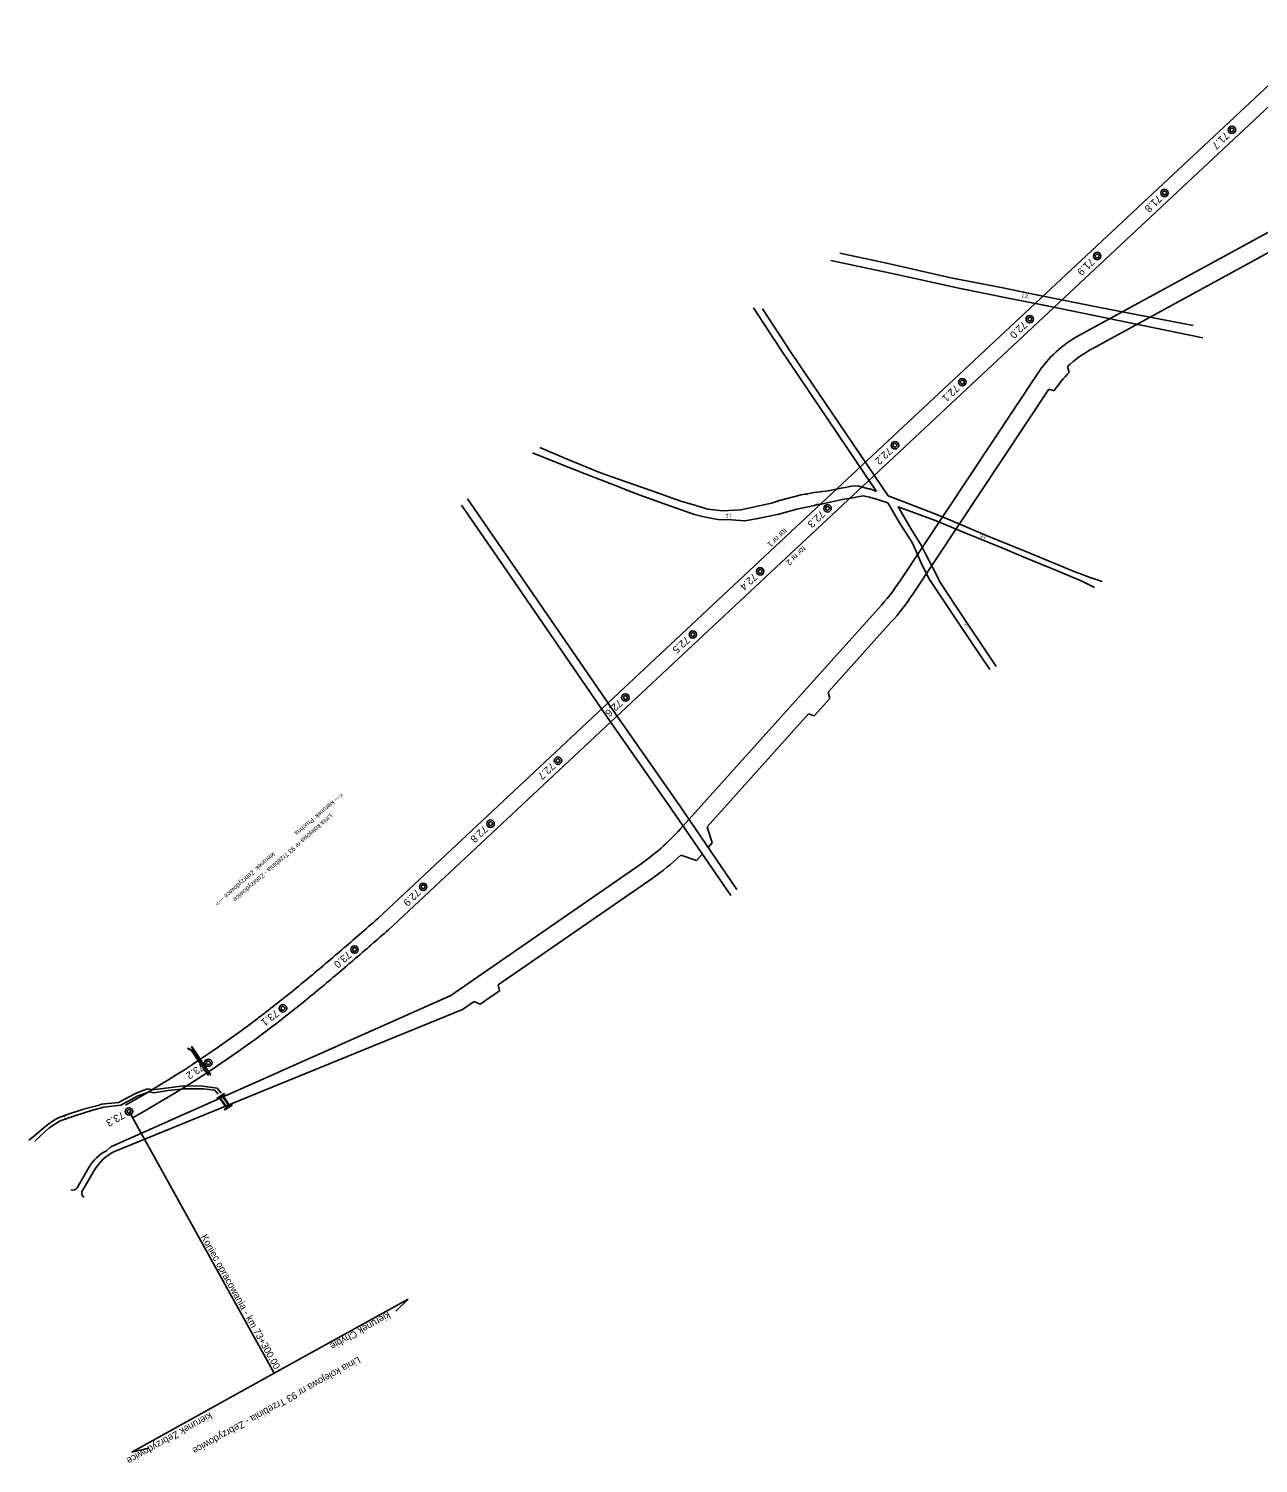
# Model space of a CAD drawing. Extents: x 6541740 to 6556805, y 5525233 to 5530361.
# Drawn here: x 6554409 to 6554742, y 5525232.8 to 5525621.4 of the extents above; entities that cross this region are included whole.
import ezdxf

# ---------------------------------------------------------------- set-up
doc = ezdxf.new("R2010")
doc.units = 0
for name, color, linetype in [('Default', 7, 'Continuous'), ('TOR_PS_OPIS_T-numeracja torow i rozjazdow', 7, 'Continuous'), ('TOR_SCH-hektometry', 7, 'Continuous'), ('TOR_SCH-obiekty projektowane', 7, 'Continuous'), ('TOR_SCH-opisy glowne', 7, 'Continuous'), ('TOR_SCH-przejazdy+drogi istniejace', 7, 'Continuous'), ('TOR_SCH-przejazdy+drogi projektowane', 7, 'Continuous'), ('TOR_SCH-tory projektowane', 7, 'Continuous')]:
    doc.layers.add(name, color=color, linetype=linetype)

# ---------------------------------------------------------------- blocks, each defined once
blk = doc.blocks.new('4010_1')
at = {"layer": 'Default'}
for radius in [0.75, 0.375]:
    blk.add_circle((0, 0), radius, dxfattribs=at)

msp = doc.modelspace()

# ---------------------------------------------------------------- linework, layer by layer
at = {"layer": 'TOR_SCH-obiekty projektowane'}
for p, q in [((6554453.97, 5525344.45), (6554453.14, 5525345.69)), ((6554454.09, 5525344.41), (6554453.2, 5525345.73)), ((6554453.15, 5525344.65), (6554456.99, 5525338.9)), ((6554453.55, 5525344.17), (6554457.11, 5525338.86)), ((6554453.97, 5525344.45), (6554457.52, 5525339.14)), ((6554454.96, 5525342.96), (6554454.02, 5525344.37)), ((6554454.09, 5525344.41), (6554457.53, 5525339.26)), ((6554456.99, 5525338.9), (6554457.68, 5525337.87)), ((6554457.11, 5525338.86), (6554457.75, 5525337.9)), ((6554457.35, 5525338.36), (6554457.89, 5525338.72)), ((6554457.39, 5525338.3), (6554457.93, 5525338.66)), ((6554457.52, 5525339.14), (6554458.27, 5525338.02)), ((6554457.53, 5525339.26), (6554458.33, 5525338.06)), ((6554460.65, 5525331.93), (6554462.55, 5525329.1)), ((6554460.8, 5525332.02), (6554462.69, 5525329.19)), ((6554461.41, 5525332.41), (6554463.31, 5525329.58)), ((6554461.56, 5525332.5), (6554463.45, 5525329.67))]:
    msp.add_line(p, q, dxfattribs=at)
for points in [[(6554453.14, 5525345.69), (6554453.2, 5525345.73)], [(6554453.55, 5525344.17), (6554453.2, 5525344.7), (6554452.14, 5525345.26), (6554452.06, 5525345.21)], [(6554452.06, 5525345.21), (6554453.15, 5525344.65)], [(6554453.15, 5525344.64), (6554453.69, 5525345)], [(6554453.19, 5525344.58), (6554453.73, 5525344.94)], [(6554457.68, 5525337.87), (6554457.75, 5525337.9)], [(6554458.33, 5525338.06), (6554458.27, 5525338.02)]]:
    msp.add_lwpolyline(points, dxfattribs=at)
for points in [[(6554461.99, 5525333.01), (6554462.1, 5525332.84), (6554460.13, 5525331.6), (6554460.02, 5525331.76)], [(6554463.99, 5525330.01), (6554464.1, 5525329.84), (6554462.12, 5525328.6), (6554462.02, 5525328.76)]]:
    msp.add_lwpolyline(points, close=True, dxfattribs=at)
at = {"layer": 'TOR_SCH-opisy glowne'}
for p, q in [((6554436.19, 5525328.13), (6554475.54, 5525257.21)), ((6554476.34, 5525257.66), (6554511.76, 5525277.31)), ((6554511.76, 5525277.31), (6554508.41, 5525274.02)), ((6554476.34, 5525257.66), (6554437, 5525235.83)), ((6554437, 5525235.81), (6554441.57, 5525236.92))]:
    msp.add_line(p, q, dxfattribs=at)
at = {"layer": 'TOR_SCH-przejazdy+drogi istniejace'}
for points in [[(6554724.4, 5525541.04), (6554699.11, 5525545.93), (6554682.35, 5525549.25), (6554672.35, 5525551.33), (6554658.77, 5525553.93), (6554641.79, 5525557.81), (6554628.67, 5525560.6)], [(6554727.02, 5525537.73), (6554684.42, 5525546.42), (6554674.7, 5525548.35), (6554660.94, 5525551.16), (6554644.1, 5525554.84), (6554626.22, 5525558.63)], [(6554638.63, 5525496.09), (6554612.47, 5525534.9), (6554605.27, 5525545.87)], [(6554607.75, 5525545.53), (6554615.61, 5525533.57), (6554641.73, 5525494.9)], [(6554545.42, 5525506.55), (6554553.79, 5525503.19), (6554559.75, 5525500.87), (6554567.67, 5525497.76), (6554573.38, 5525495.55), (6554579.87, 5525493.22), (6554585.68, 5525491.13), (6554589.37, 5525489.82), (6554591.85, 5525489.25), (6554595.66, 5525488.5), (6554599.38, 5525488.39), (6554602.99, 5525488.11), (6554606.5, 5525488.73), (6554612.19, 5525489.92), (6554617.07, 5525491.28), (6554621.85, 5525492.29)], [(6554619.19, 5525495.33), (6554618.24, 5525495.15), (6554612.3, 5525493.6), (6554610.19, 5525492.94), (6554601.87, 5525491.08), (6554596.87, 5525490.88), (6554592.94, 5525491.33), (6554588.76, 5525492.52), (6554585.93, 5525493.41), (6554577.01, 5525496.49), (6554568.48, 5525499.5), (6554563.89, 5525501.11), (6554559.93, 5525502.78), (6554554.87, 5525504.8), (6554547.4, 5525507.95)], [(6554633.61, 5525497.56), (6554632.81, 5525497.64), (6554631.84, 5525497.54), (6554630.94, 5525497.36), (6554630.22, 5525497.16), (6554629.52, 5525497.06), (6554625.51, 5525496.3), (6554621.76, 5525495.78), (6554619.93, 5525495.44), (6554619.65, 5525495.33), (6554619.19, 5525495.33)], [(6554638.63, 5525496.09), (6554636.62, 5525496.88), (6554636.73, 5525496.74), (6554633.93, 5525497.51), (6554633.61, 5525497.56)], [(6554527.88, 5525494.07), (6554540.88, 5525475.2), (6554567.9, 5525435.86), (6554585.5, 5525410.63), (6554600.82, 5525388.31)], [(6554621.85, 5525492.29), (6554622.41, 5525492.58), (6554623.2, 5525492.57), (6554623.65, 5525492.66), (6554629.31, 5525493.88), (6554632.26, 5525494.32)], [(6554632.26, 5525494.32), (6554632.99, 5525494.5), (6554633.58, 5525494.65), (6554634.97, 5525494.86), (6554636.75, 5525494.55), (6554638.89, 5525493.94), (6554641.66, 5525492.98), (6554641.66, 5525492.98)], [(6554699.68, 5525471.74), (6554696.21, 5525472.86), (6554692.18, 5525474.4), (6554679.02, 5525479.78), (6554668.55, 5525484.05), (6554658.86, 5525488.2), (6554654.43, 5525490.06), (6554647.22, 5525492.79), (6554641.73, 5525494.9)], [(6554526.2, 5525492.41), (6554538.49, 5525474.58), (6554562.95, 5525438.96), (6554565.52, 5525435.22), (6554583.11, 5525410), (6554599.17, 5525386.62)], [(6554641.66, 5525492.98), (6554645.03, 5525487.31), (6554648.28, 5525482.22), (6554649.14, 5525480.27), (6554650.56, 5525477.1), (6554652.76, 5525472.51), (6554661.3, 5525459.79), (6554669.3, 5525447.89)], [(6554697.68, 5525470.04), (6554693.99, 5525471.87), (6554687.82, 5525474.48), (6554678.3, 5525478.39), (6554672.34, 5525480.92), (6554662.36, 5525485.01), (6554655.02, 5525488.04), (6554644.45, 5525491.88), (6554647.87, 5525486.03), (6554650.68, 5525481.51), (6554652.1, 5525478.85), (6554653.89, 5525475.43), (6554655.94, 5525471.3), (6554659.93, 5525465.32), (6554671.03, 5525448.65)], [(6554428.76, 5525330.1), (6554433.36, 5525330.54), (6554437.99, 5525333.02), (6554440.9, 5525334.16), (6554441.35, 5525334.24), (6554442.63, 5525334.01), (6554446.77, 5525334.55), (6554451, 5525335.08), (6554456.2, 5525335.03), (6554460.05, 5525334.44), (6554461.11, 5525333.07)], [(6554460.29, 5525332.79), (6554459.4, 5525333.89), (6554456.33, 5525334.31), (6554451.33, 5525334.28), (6554446.79, 5525333.78), (6554442.94, 5525333.19), (6554441.71, 5525333.49), (6554438.58, 5525332.33)], [(6554409.03, 5525320.35), (6554410.24, 5525321.26), (6554412.56, 5525323.29), (6554413.73, 5525324.28), (6554415.48, 5525325.53), (6554416.84, 5525326.3), (6554419.2, 5525327.2), (6554423.9, 5525328.74), (6554428.13, 5525329.86), (6554428.76, 5525330.1)], [(6554429.38, 5525329.33), (6554433.97, 5525329.81), (6554438.58, 5525332.33)], [(6554429.38, 5525329.33), (6554425.99, 5525328.43), (6554421.76, 5525327.07), (6554417.52, 5525325.58), (6554414.57, 5525323.72), (6554412.22, 5525321.52), (6554410.77, 5525320.15), (6554410.77, 5525320.15)]]:
    msp.add_lwpolyline(points, dxfattribs=at)
at = {"layer": 'TOR_SCH-przejazdy+drogi projektowane'}
for p, q in [((6554764.56, 5525577.16), (6554693.62, 5525538.42)), ((6554764.57, 5525571.64), (6554696.97, 5525534.73)), ((6554690.81, 5525528.3), (6554690.31, 5525529.91)), ((6554682.18, 5525527.94), (6554644.98, 5525471.87)), ((6554685.29, 5525523.82), (6554648.44, 5525468.28)), ((6554686.75, 5525523.38), (6554685.29, 5525523.82)), ((6554639.18, 5525464.37), (6554585.45, 5525404.6)), ((6554642.61, 5525460.74), (6554625.48, 5525441.68)), ((6554621.76, 5525435.3), (6554626.01, 5525440.03)), ((6554625.48, 5525441.68), (6554626.01, 5525440.03)), ((6554620.22, 5525435.83), (6554592.72, 5525405.24)), ((6554620.22, 5525435.83), (6554621.76, 5525435.3)), ((6554592.72, 5525405.24), (6554594.12, 5525400.87)), ((6554593.03, 5525399.66), (6554594.12, 5525400.87)), ((6554585.59, 5525397.58), (6554589.84, 5525396.11)), ((6554589.84, 5525396.11), (6554591.43, 5525397.88)), ((6554574.48, 5525394.95), (6554523.3, 5525359.52)), ((6554577.86, 5525391.28), (6554536.15, 5525362.4)), ((6554536.15, 5525362.4), (6554536.54, 5525360.86)), ((6554523.3, 5525359.52), (6554431.28, 5525318.52)), ((6554523.3, 5525359.52), (6554523.09, 5525359.38)), ((6554529.64, 5525357.89), (6554526.51, 5525355.72)), ((6554529.64, 5525357.89), (6554531.27, 5525357.22)), ((6554531.27, 5525357.22), (6554536.54, 5525360.86)), ((6554526.51, 5525355.72), (6554432.22, 5525317.29)), ((6554430.11, 5525317.51), (6554431.28, 5525318.52)), ((6554425.32, 5525312.99), (6554422.14, 5525307.48)), ((6554426.78, 5525312.15), (6554423.56, 5525306.69))]:
    msp.add_line(p, q, dxfattribs=at)
for centre, radius, start, end in [((6554435.28, 5525307.24), 11.5, 116.6963, 149.9534), ((6554438.14, 5525305.58), 13.12, 116.8109, 149.9534), ((6554421, 5525308.14), 1.31, 246.6218, 329.9534), ((6554424.7, 5525306.04), 1.31, 149.9534, 240.4975)]:
    msp.add_arc(centre, radius, start, end, dxfattribs=at)
for centre, major_axis, start_param, end_param in [((6555030.42, 5525166.83), (-343.43, 366.83), 6.218732, 6.342331), ((6555030.42, 5525166.83), (-340.01, 363.18), 6.218732, 6.284285), ((6555030.42, 5525166.83), (-338.99, 362.08), 0.00704, 0.058091), ((6553953.68, 5526188.7), (-681.73, 728.18), 3.16316, 3.200739), ((6553953.68, 5526188.7), (-685.15, 731.83), 3.16316, 3.200739), ((6553899.95, 5526128.94), (-681.73, 728.18), 3.104606, 3.16316), ((6553899.95, 5526128.94), (-685.15, 731.83), 3.104606, 3.144299)]:
    msp.add_ellipse(centre, major_axis=major_axis, ratio=0.25, start_param=start_param, end_param=end_param, dxfattribs=at)
at = {"layer": 'TOR_SCH-tory projektowane'}
for p, q in [((6554761.12, 5525621.44), (6554611.29, 5525481.24)), ((6554764.11, 5525618.43), (6554614.16, 5525478.15)), ((6554611.29, 5525481.24), (6554503.49, 5525380.32)), ((6554614.16, 5525478.15), (6554506.36, 5525377.25))]:
    msp.add_line(p, q, dxfattribs=at)
for points in [[(6554503.49, 5525380.32), (6554502.88, 5525379.79), (6554502.28, 5525379.26), (6554501.67, 5525378.74), (6554501.07, 5525378.21), (6554500.46, 5525377.68), (6554499.86, 5525377.16), (6554499.25, 5525376.63), (6554498.65, 5525376.11), (6554498.04, 5525375.58), (6554497.44, 5525375.06), (6554496.83, 5525374.53), (6554496.22, 5525374.01), (6554495.62, 5525373.48), (6554495.01, 5525372.96), (6554494.4, 5525372.44), (6554493.79, 5525371.91), (6554493.18, 5525371.39), (6554492.58, 5525370.87), (6554491.97, 5525370.35), (6554491.36, 5525369.83), (6554490.75, 5525369.31), (6554490.14, 5525368.79), (6554489.52, 5525368.27), (6554488.91, 5525367.75), (6554488.3, 5525367.23), (6554487.69, 5525366.72), (6554487.07, 5525366.2), (6554486.46, 5525365.68), (6554485.84, 5525365.17), (6554485.23, 5525364.66), (6554484.61, 5525364.14), (6554483.99, 5525363.63), (6554483.38, 5525363.12), (6554482.76, 5525362.61), (6554482.14, 5525362.1), (6554481.52, 5525361.59), (6554480.89, 5525361.09), (6554480.27, 5525360.58), (6554479.65, 5525360.08), (6554479.02, 5525359.58), (6554478.4, 5525359.07), (6554477.77, 5525358.57), (6554477.14, 5525358.07), (6554476.52, 5525357.57), (6554475.89, 5525357.08), (6554475.26, 5525356.58), (6554474.62, 5525356.09), (6554473.99, 5525355.6), (6554473.36, 5525355.1), (6554472.72, 5525354.62), (6554472.09, 5525354.13), (6554471.45, 5525353.64), (6554470.81, 5525353.16)], [(6554506.55, 5525377.44), (6554505.95, 5525376.91), (6554505.35, 5525376.39), (6554504.75, 5525375.87), (6554504.15, 5525375.35), (6554503.55, 5525374.83), (6554502.95, 5525374.31), (6554502.35, 5525373.79), (6554501.76, 5525373.27), (6554501.16, 5525372.75), (6554500.56, 5525372.23), (6554499.96, 5525371.71), (6554499.36, 5525371.19), (6554498.76, 5525370.68), (6554498.16, 5525370.16), (6554497.55, 5525369.64), (6554496.95, 5525369.12), (6554496.35, 5525368.61), (6554495.75, 5525368.09), (6554495.15, 5525367.57), (6554494.54, 5525367.06), (6554493.94, 5525366.54), (6554493.34, 5525366.03), (6554492.73, 5525365.52), (6554492.13, 5525365), (6554491.52, 5525364.49), (6554490.91, 5525363.98), (6554490.31, 5525363.47), (6554489.7, 5525362.96), (6554489.09, 5525362.45), (6554488.48, 5525361.94), (6554487.87, 5525361.44), (6554487.26, 5525360.93), (6554486.65, 5525360.43), (6554486.03, 5525359.92), (6554485.42, 5525359.42), (6554484.81, 5525358.92), (6554484.19, 5525358.42), (6554483.58, 5525357.92), (6554482.96, 5525357.42), (6554482.34, 5525356.92), (6554481.72, 5525356.42), (6554481.1, 5525355.93), (6554480.48, 5525355.43), (6554479.86, 5525354.94), (6554479.24, 5525354.45), (6554478.61, 5525353.96), (6554477.99, 5525353.47), (6554477.36, 5525352.98), (6554476.74, 5525352.5), (6554476.11, 5525352.01), (6554475.48, 5525351.53), (6554474.85, 5525351.05)]]:
    msp.add_lwpolyline(points, dxfattribs=at)
for centre, radius, start, end in [((6554282.16, 5525602.29), 312.5, 299.3305, 307.1342), ((6554285.04, 5525600.56), 313.5, 299.0221, 307.2608)]:
    msp.add_arc(centre, radius, start, end, dxfattribs=at)

# ---------------------------------------------------------------- block references
at = {"layer": 'TOR_SCH-hektometry'}
for p, xscale, yscale, rotation in [((6554734.86, 5525594.03), 1.3459632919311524, 1.345963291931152, 18.110655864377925), ((6554716.61, 5525576.95), 1.3459632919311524, 1.345963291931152, 18.110655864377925), ((6554698.36, 5525559.86), 1.3459632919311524, 1.345963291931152, 18.110655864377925), ((6554680.11, 5525542.77), 1.3459632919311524, 1.345963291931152, 18.110655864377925), ((6554661.86, 5525525.69), 1.3459632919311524, 1.345963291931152, 18.110655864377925), ((6554643.61, 5525508.6), 1.3459632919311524, 1.345963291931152, 18.110655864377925), ((6554625.36, 5525491.52), 1.3459632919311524, 1.345963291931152, 18.110655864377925), ((6554607.11, 5525474.43), 1.3459632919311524, 1.345963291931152, 18.110655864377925), ((6554588.86, 5525457.34), 1.3459632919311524, 1.345963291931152, 18.110655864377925), ((6554570.61, 5525440.26), 1.3459632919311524, 1.345963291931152, 18.110655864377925), ((6554552.36, 5525423.17), 1.3459632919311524, 1.345963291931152, 18.110655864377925), ((6554534.11, 5525406.09), 1.3459632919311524, 1.345963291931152, 18.110655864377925), ((6554515.86, 5525389), 1.3459632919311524, 1.345963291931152, 18.110655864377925), ((6554497.27, 5525372.01), 1.3459632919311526, 1.3459632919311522, 14.818671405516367), ((6554477.88, 5525356.07), 1.3459632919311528, 1.3459632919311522, 10.5307064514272), ((6554457.66, 5525341.33), 1.3459632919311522, 1.3459632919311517, 7.507908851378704), ((6554436.19, 5525328.13), 1.345963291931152, 1.3459632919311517, 3.3892881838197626)]:
    msp.add_blockref('4010_1', p, dxfattribs=dict(at, xscale=xscale, yscale=yscale, rotation=rotation))

# ---------------------------------------------------------------- texts
at = {"layer": 'TOR_PS_OPIS_T-numeracja torow i rozjazdow'}
for s, p in [('tor nr 1', (6554613.59, 5525486.24)), ('tor nr 2', (6554618.67, 5525481.39))]:
    msp.add_text(s, height=1.5, rotation=223.113, dxfattribs=at).set_placement(p)
at = {"layer": 'TOR_SCH-hektometry'}
for s, rotation, p in [('71.7', 224.4899, (6554732.99, 5525593.63)), ('71.8', 224.4899, (6554714.74, 5525576.55)), ('71.9', 224.4899, (6554696.49, 5525559.46)), ('72.0', 224.4899, (6554678.24, 5525542.38)), ('72.1', 224.4899, (6554659.87, 5525525.18)), ('72.2', 224.4899, (6554641.73, 5525508.2)), ('72.3', 224.4899, (6554623.49, 5525491.12)), ('72.4', 222.9381, (6554605.23, 5525474.08)), ('72.5', 222.9229, (6554586.98, 5525457)), ('72.6', 223.1646, (6554568.73, 5525439.91)), ('72.7', 223.0791, (6554550.48, 5525422.82)), ('72.8', 223.0391, (6554532.23, 5525405.74)), ('72.9', 224.4899, (6554513.99, 5525388.6)), ('73.0', 221.1979, (6554495.38, 5525371.72)), ('73.1', 216.91, (6554475.85, 5525355.83)), ('73.2', 213.8872, (6554455.75, 5525341.28)), ('73.3', 209.7685, (6554434.28, 5525328.22))]:
    msp.add_text(s, height=2, rotation=rotation, dxfattribs=at).set_placement(p)
at = {"layer": 'TOR_SCH-opisy glowne'}
for s, height, rotation, p in [('<--- kierunek: Pruchna', 1.2202, 220.2174, (6554493.67, 5525414.49)), ('Linia kolejowa nr 93 Trzebinia - Zebrzydowice', 1.2535, 221.141, (6554490.68, 5525408.84)), ('kierunek: Zebrzydowice --->', 1.2202, 221.7194, (6554475.03, 5525398.45)), ('Koniec opracowania - km 73+300,00 ', 1.9, 299.0209, (6554455.58, 5525294.22)), ('kierunek Chybie', 1.9, 209.0209, (6554506.36, 5525273.92)), ('Linia kolejowa nr 93 Trzebinia - Zebrzydowice', 1.9, 209.0209, (6554498.22, 5525261.81)), ('kierunek Zebrzydowice', 1.9, 209.0209, (6554458.04, 5525246.68))]:
    msp.add_text(s, height=height, rotation=rotation, dxfattribs=at).set_placement(p)
at = {"layer": 'TOR_SCH-przejazdy+drogi istniejace'}
for height, rotation, p in [(1.184, 348.596, (6554677.97, 5525548.74)), (1, 180.134, (6554599.21, 5525489.85)), (1, 155.3631, (6554668.19, 5525483.79)), (0.757, 123.2781, (6554663.33, 5525459.45)), (0.8, 202.9642, (6554419.44, 5525327.15))]:
    msp.add_text('j.z.', height=height, rotation=rotation, dxfattribs=at).set_placement(p)

doc.saveas('drawing.dxf')
